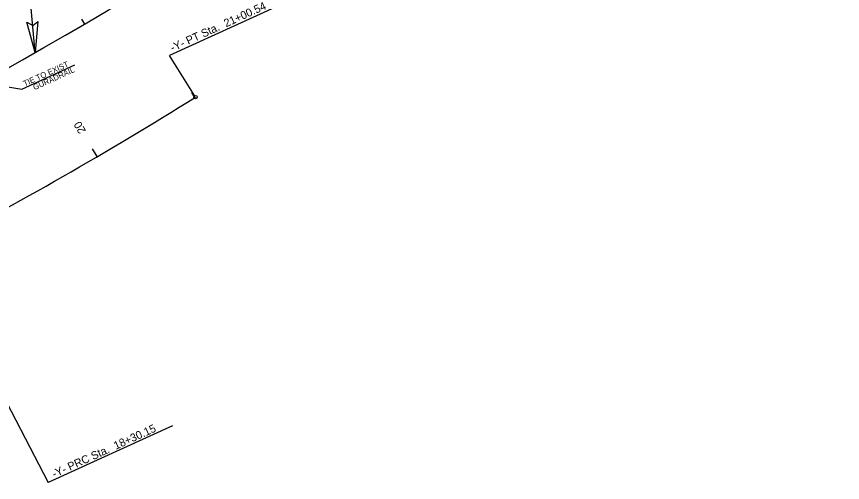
# Model space of a CAD drawing. Extents: x 2242984 to 2250974, y 661492 to 664681.
# Drawn here: x 2250250 to 2250973, y 663613 to 664020 of the extents above; entities that cross this region are included whole.
import ezdxf

# ---------------------------------------------------------------- set-up
doc = ezdxf.new("R2010")
doc.units = 0
for name, color, linetype in [('Prop Dimension', 7, 'Continuous'), ('Prop Dimension Text', 7, 'Continuous'), ('Prop Horizontal Alignment', 7, 'Continuous'), ('Prop Horizontal Alignment Station Label', 7, 'Continuous'), ('Prop Horizontal Alignment Tick Label', 7, 'Continuous'), ('Prop Horizontal Alignment Tick Large', 7, 'Continuous'), ('Prop Horizontal Alignment Tick Small', 7, 'Continuous'), ('Prop Terminator CELL', 7, 'Continuous')]:
    doc.layers.add(name, color=color, linetype=linetype)

msp = doc.modelspace()

# ---------------------------------------------------------------- linework, layer by layer
at = {"layer": 'Prop Dimension'}
for p, q in [((2250255.11, 663956.78), (2250301.46, 663978.01)), ((2250224.53, 663961.77), (2250255.11, 663956.78))]:
    msp.add_line(p, q, dxfattribs=at)
at = {"layer": 'Prop Horizontal Alignment'}
for centre, radius, start, end in [((2247423.42, 668962.88), 5729.58, 294.43013, 308.28013), ((2248552.07, 666917.75), 3500, 297.57881, 302.00527)]:
    msp.add_arc(centre, radius, start, end, dxfattribs=at)
at = {"layer": 'Prop Horizontal Alignment Station Label'}
for p, q in [((2250266.8, 663988.62), (2250255.13, 664117.02)), ((2250480.34, 664029.82), (2250384.35, 663986.08)), ((2250406.26, 663951.02), (2250384.35, 663986.08)), ((2250173.15, 663814.11), (2250278.27, 663612.84)), ((2250387.05, 663662.41), (2250278.27, 663612.84))]:
    msp.add_line(p, q, dxfattribs=at)
msp.add_circle((2250407.06, 663949.75), 1.5, dxfattribs=at)
msp.add_circle((2250407.06, 663949.75), 1.5, dxfattribs=at)
at = {"layer": 'Prop Horizontal Alignment Tick Large'}
msp.add_line((2250321.04, 663897.7), (2250317, 663904.6), dxfattribs=at)
at = {"layer": 'Prop Horizontal Alignment Tick Small'}
for p, q in [((2250310.1, 664013.63), (2250307.58, 664017.95)), ((2250406.59, 663949.46), (2250403.95, 663953.7))]:
    msp.add_line(p, q, dxfattribs=at)
at = {"layer": 'Prop Terminator CELL'}
msp.add_lwpolyline([(2250268.99, 664015.93), (2250266.8, 663988.62), (2250259.56, 664015.23), (2250264.66, 664012.23)], close=True, dxfattribs=at)

# ---------------------------------------------------------------- texts
at = {"layer": 'Prop Dimension Text'}
for s, p in [('TIE TO EXIST', (2250257.7, 663958.98)), ('GURADRAIL', (2250266.31, 663955.71))]:
    msp.add_text(s, height=5, rotation=24.49794, dxfattribs=at).set_placement(p)
at = {"layer": 'Prop Horizontal Alignment Station Label'}
for s, p in [('-Y- PT Sta.  21+00.54', (2250386.91, 663989.3)), ('-Y- PRC Sta.  18+30.15', (2250283.43, 663616.79))]:
    msp.add_text(s, height=7, rotation=24.49794, dxfattribs=at).set_placement(p)
at = {"layer": 'Prop Horizontal Alignment Tick Label'}
msp.add_text('20', height=7, rotation=120.35934, dxfattribs=at).set_placement((2250311.42, 663920.34))

doc.saveas('drawing.dxf')
